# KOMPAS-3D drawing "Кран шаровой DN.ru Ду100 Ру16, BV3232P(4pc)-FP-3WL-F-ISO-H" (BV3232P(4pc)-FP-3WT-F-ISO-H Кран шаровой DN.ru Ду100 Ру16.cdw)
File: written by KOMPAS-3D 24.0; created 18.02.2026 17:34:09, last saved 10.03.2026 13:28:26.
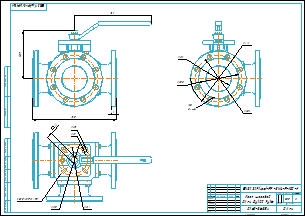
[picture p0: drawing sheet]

Document properties: Автор: R2D2; Форматы листов документа: A2; Полное имя файла: ..\..\BV3232P(4pc)-FP-3WL-F-ISO-H Кран шаровой DN.ru Ду15-100 Ру16\DN100\BV3232P(4pc)-FP-3WL-F-ISO-H Кран шаровой DN.ru Ду100 Ру16.cdw; Масса: 58.5; Наименование: Кран шаровой DN.ru Ду100 Ру16; Количество листов документа: 1; Примечание: D160-36363

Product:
- Part/product: Кран шаровой DN.ru Ду100 Ру16  | designation BV3232P(4pc)-FP-3WL-F-ISO-H
    Масса: 58.5
    Раздел спецификации: Прочие изделия
    Форматы листов документа: A2
    Примечание: D160-36363

Views: Проекционный вид 2
Referenced files in E:\Работа\Зайцев\BV3232P(4pc)-FP-3WL-F-ISO-H Кран шаровой DN.ru Ду15-100 Ру16\DN100\: BV3232P(4pc)-FP-3WL-F-ISO-H Кран шаровой DN.ru Ду100 Ру16.m3d
Referenced files in E:\Работа\Зайцев\Для компаса\: чертеж DN.ru А3.cdt
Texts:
  BV3232P(4pc)-FP-3WL-F-ISO-H
  чертеж DN.ru А3.cdt
  Кран шаровой
  DN.ru Ду100 Ру16
  Кран шаровой DN.ru Ду100 Ру16
  BV3232P(4pc)-FP-3WL-F-ISO-H Кран шаровой DN.ru Ду100 Ру16
Dimensions and other numbers on the sheet: 0; 3; 4; 220; 180; 158; 18; 8 отв.; 100; 1:2; 1; 2; 58,5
